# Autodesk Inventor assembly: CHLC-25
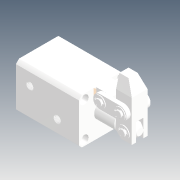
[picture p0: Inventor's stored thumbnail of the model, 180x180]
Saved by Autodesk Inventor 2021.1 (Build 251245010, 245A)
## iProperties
Created: 2019-04
Part Number: CHLC-25
Description: STEP AP214
Document SubType Name: Assembly
Designer: user
Title: CHLC-25.STEP
Revision Number: ÈÎºÎ
Sending System: SolidWorks 2016
Preprocessor: SwSTEP 2.0
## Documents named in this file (10)
- D:\Vault_2016\Projekty\Clamptek\Hydraulic\CHLC\CHLC-25\Inventor\CHLC-25\CHLC-25.iam
- D:\Vault_2016\Projekty\Clamptek\Hydraulic\CHLC\CHLC-25\Inventor\CHLC-25\CHLC-25-01_ASM.ipt
- D:\Vault_2016\Projekty\Clamptek\Hydraulic\CHLC\CHLC-25\Inventor\CHLC-25\CHLC-25BT.ipt
- D:\Vault_2016\Projekty\Clamptek\Hydraulic\CHLC\CHLC-25\Inventor\CHLC-25\CHLC-25ZC.ipt
- D:\Vault_2016\Projekty\Clamptek\Hydraulic\CHLC\CHLC-25\Inventor\CHLC-25\CHLC-25LG.ipt
- D:\Vault_2016\Projekty\Clamptek\Hydraulic\CHLC\CHLC-25\Inventor\CHLC-25\CHLC-25HSG.ipt
- D:\Vault_2016\Projekty\Clamptek\Hydraulic\CHLC\CHLC-25\Inventor\CHLC-25\CHLC-25DX.ipt
- D:\Vault_2016\Projekty\Clamptek\Hydraulic\CHLC\CHLC-25\Inventor\CHLC-25\CHLC-25CX.ipt
- D:\Vault_2016\Projekty\Clamptek\Hydraulic\CHLC\CHLC-25\Inventor\CHLC-25\CHLC-25KKDC.ipt
- D:\Vault_2016\Projekty\Clamptek\Hydraulic\CHLC\CHLC-25\Inventor\CHLC-25\Ñ¹±Û.ipt
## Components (16 placed, 16 different names)
1. CHLC-25-01_ASM_1
2. CHLC-25BT_2
3. CHLC-25ZC_3
4. CHLC-25LG_4
5. CHLC-25LG_5
6. CHLC-25HSG_6
7. CHLC-25DX_7
8. CHLC-25CX_8
9. CHLC-25CX_9
10. CHLC-25KKDC_10
11. CHLC-25KKDC_11
12. CHLC-25KKDC_12
13. CHLC-25KKDC_13
14. CHLC-25KKDC_14
15. CHLC-25KKDC_15
16. Ñ¹±Û_16
